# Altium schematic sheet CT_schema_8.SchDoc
size 277 x 170 mm
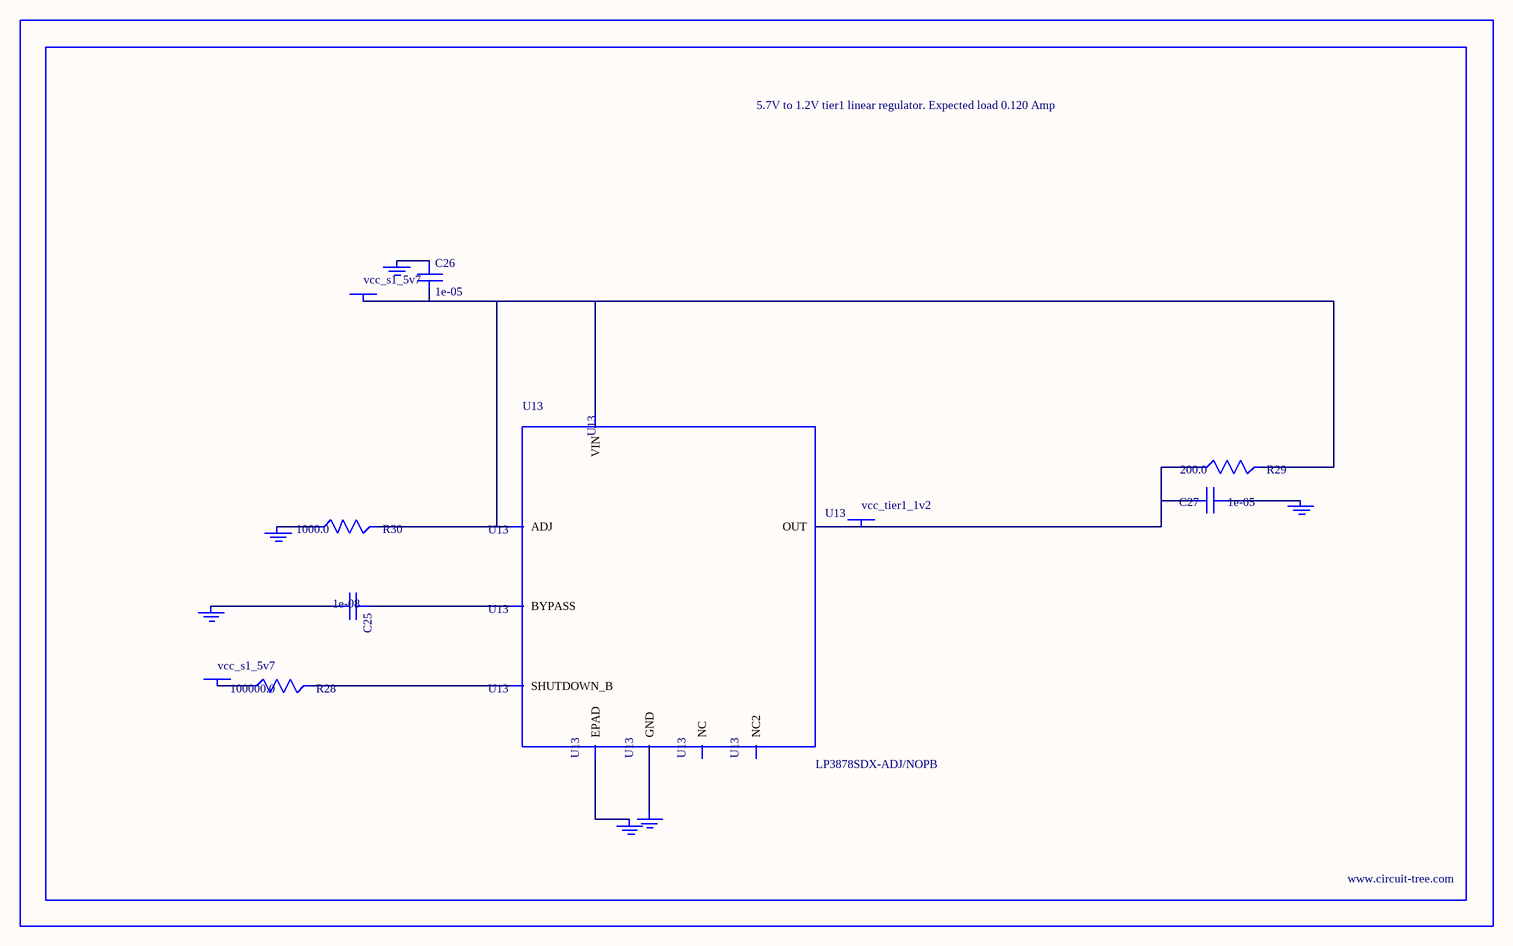
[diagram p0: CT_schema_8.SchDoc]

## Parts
BORDER7  (no value)
C25  1e-08  [C0402]
C26  1e-05  [C1206]
C27  1e-05  [C0805]
GND_INSTANCE_7_0  (no value)
GND_INSTANCE_7_1  (no value)
GND_INSTANCE_7_2  (no value)
GND_INSTANCE_7_3  (no value)
GND_INSTANCE_7_4  (no value)
GND_INSTANCE_7_5  (no value)
POWER_INSTANCE_7_0  vcc_s1_5v7
POWER_INSTANCE_7_1  vcc_s1_5v7
POWER_INSTANCE_7_2  vcc_tier1_1v2
R28  100000.0  [R0603]
R29  200.0  [R0603]
R30  1000.0  [R0603]
U13  LP3878SDX-ADJ/NOPB  [WSON-8]

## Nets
NetC25_1: C25.1 U13.1(BYPASS)
NetC25_2: C25.2 GND_INSTANCE_7_0.0(GND)
NetC26_1: C26.1 GND_INSTANCE_7_1.0(GND)
NetC26_2: C26.2 POWER_INSTANCE_7_0.0(PWR) R29.2 R30.2 U13.4(VIN) U13.6(ADJ)
NetC27_1: C27.1 GND_INSTANCE_7_2.0(GND)
NetC27_2: C27.2 POWER_INSTANCE_7_2.0(PWR) R29.1 U13.5(OUT)
NetGND_INSTANCE_7_3_0: GND_INSTANCE_7_3.0(GND) R30.1
NetGND_INSTANCE_7_4_0: GND_INSTANCE_7_4.0(GND) U13.PAD(EPAD)
NetGND_INSTANCE_7_5_0: GND_INSTANCE_7_5.0(GND) U13.3(GND)
NetPOWER_INSTANCE_7_1_0: POWER_INSTANCE_7_1.0(PWR) R28.1
NetR28_2: R28.2 U13.8(SHUTDOWN_B)

Not connected (* = marked no-connect by the designer): U13 2(NC) 7(NC2)

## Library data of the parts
BORDER7 = BORDER_PAGE7
C25 = C0402C103K3RAC
C26 = C1206C106K3RACTU
C27 = GRM219R60J106ME19D
GND_INSTANCE_7_0-GND_INSTANCE_7_5 = GND
POWER_INSTANCE_7_0-POWER_INSTANCE_7_2 = PWR
R28 = RC0603JR-07100KL
R29 = RC0603JR-07200RL
R30 = RC0603JR-071KL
